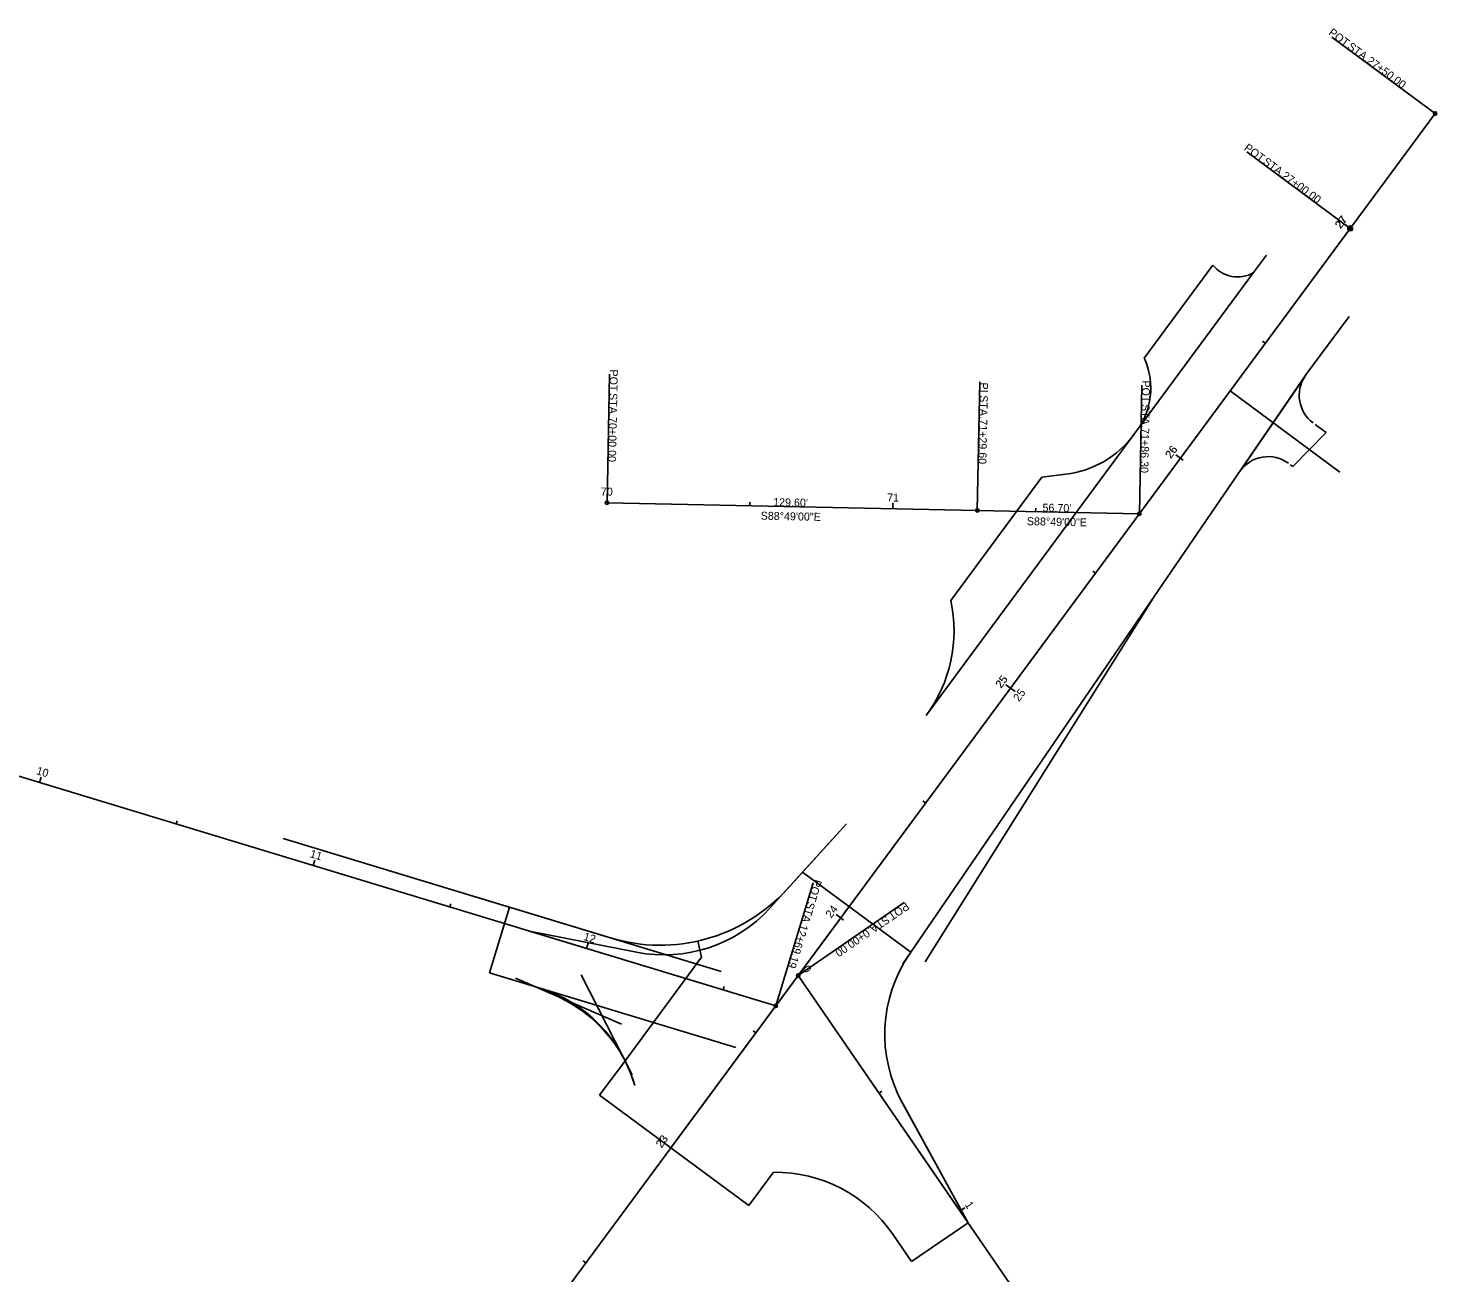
# Model space of a CAD drawing. Extents: x 1323137 to 1326838, y 458936 to 461644.
# Drawn here: x 1325088.4 to 1325581.3, y 460252 to 460687.5 of the extents above; entities that cross this region are included whole.
import ezdxf

# ---------------------------------------------------------------- set-up
doc = ezdxf.new("R2010")
doc.units = 0
for name, color, linetype in [('_CIVIL_CONSTRUCTION', 7, 'Continuous'), ('CM_Corridor_Point_Control', 7, 'Continuous'), ('CM_Corridor_Range_Final', 7, 'Continuous'), ('Default', 7, 'Continuous'), ('DT_P_Graded_Shoulder', 7, 'Continuous'), ('DT_P_Tie', 7, 'Continuous'), ('MD_P_ACB_B', 7, 'Continuous'), ('MD_P_ACB_T', 7, 'Continuous'), ('MD_P_ACSC_B', 7, 'Continuous'), ('MD_P_Surface_Asphalt_Concrete_Intermediate_Course', 7, 'Continuous'), ('PV_P_Shoulder', 7, 'Continuous'), ('RD_P_GR_Lt', 7, 'Continuous'), ('SG_P_Conduit', 7, 'Continuous'), ('SG_P_Mast_Arm', 7, 'Continuous'), ('SN_P_Signs', 7, 'Continuous'), ('SN_X_Public', 7, 'Continuous')]:
    doc.layers.add(name, color=color, linetype=linetype)

msp = doc.modelspace()

# ---------------------------------------------------------------- linework, layer by layer
at = {"layer": '_CIVIL_CONSTRUCTION'}
for p, q in [((1325551, 460617.41), (1325514.81, 460644.15)), ((1325350.01, 460345.38), (1325363.06, 460388.44))]:
    msp.add_line(p, q, dxfattribs=at)
for centre in [(1325551, 460617.41), (1325350.01, 460345.38)]:
    msp.add_circle(centre, 0.6, dxfattribs=at)
at = {"layer": 'CM_Corridor_Point_Control'}
msp.add_line((1325508.98, 460560.54), (1325547.43, 460532.13), dxfattribs=at)
at = {"layer": 'CM_Corridor_Range_Final'}
for p, q in [((1325551, 460617.41), (1325549.39, 460618.6)), ((1325521.29, 460577.19), (1325520.32, 460577.91)), ((1325491.57, 460536.98), (1325489.97, 460538.17)), ((1325461.86, 460496.77), (1325460.9, 460497.48)), ((1325432.15, 460456.55), (1325430.54, 460457.74)), ((1325092.4, 460423.47), (1325092.98, 460425.39)), ((1325402.44, 460416.34), (1325401.47, 460417.05)), ((1325140.25, 460408.97), (1325140.59, 460410.11)), ((1325188.1, 460394.46), (1325188.68, 460396.37)), ((1325235.94, 460379.95), (1325236.29, 460381.1)), ((1325372.72, 460376.12), (1325371.12, 460377.31)), ((1325283.79, 460365.45), (1325284.37, 460367.36)), ((1325331.64, 460350.94), (1325331.99, 460352.09)), ((1325343.01, 460335.91), (1325342.05, 460336.62)), ((1325313.3, 460295.7), (1325311.69, 460296.88)), ((1325283.59, 460255.48), (1325282.62, 460256.19))]:
    msp.add_line(p, q, dxfattribs=at)
at = {"layer": 'Default'}
msp.add_line((1325432.15, 460456.55), (1325432.15, 460456.55), dxfattribs=at)
msp.add_circle((1325551, 460617.41), 0.849, dxfattribs=at)
at = {"layer": 'DT_P_Tie'}
for p, q in [((1325517.2, 460601.95), (1325521.67, 460608)), ((1325476.34, 460546.65), (1325517.2, 460601.95)), ((1325478.93, 460572.03), (1325502.98, 460604.58)), ((1325535.76, 460566.5), (1325550.62, 460586.6)), ((1325479.24, 460571.28), (1325478.93, 460572.03)), ((1325397.28, 460364.2), (1325535.76, 460566.5)), ((1325512.37, 460532.33), (1325535.26, 460565.75)), ((1325538.79, 460548.76), (1325542.6, 460545.95)), ((1325402.67, 460446.95), (1325475.35, 460545.31)), ((1325475.35, 460545.31), (1325476.34, 460546.65)), ((1325530.94, 460534.06), (1325542.6, 460545.95)), ((1325530.04, 460534.73), (1325530.94, 460534.06)), ((1325411.24, 460487.15), (1325443.15, 460530.34)), ((1325443.15, 460530.34), (1325451.51, 460531.38)), ((1325402.23, 460360.81), (1325482.01, 460487.97)), ((1325347.71, 460379.29), (1325374.7, 460409.08)), ((1325374.7, 460409.08), (1325354.07, 460386.31)), ((1325374.7, 460409.08), (1325354.07, 460386.31)), ((1325359.37, 460392.2), (1325374.7, 460409.08)), ((1325330.94, 460357.42), (1325177.6, 460403.91)), ((1325292.19, 460369.17), (1325177.6, 460403.91)), ((1325292.19, 460369.17), (1325177.6, 460403.91)), ((1325347.92, 460379.57), (1325359.37, 460392.2)), ((1325347.94, 460379.6), (1325359.37, 460392.2)), ((1325397.28, 460364.2), (1325359.37, 460392.2)), ((1325313.3, 460295.7), (1325375.69, 460380.14)), ((1325256.83, 460379.89), (1325249.86, 460356.93)), ((1325292.19, 460369.17), (1325256.83, 460379.89)), ((1325263.79, 460371.51), (1325301.27, 460364.12)), ((1325263.79, 460371.51), (1325350.01, 460345.38)), ((1325263.79, 460371.51), (1325301.23, 460364.13)), ((1325394.44, 460360.08), (1325397.28, 460364.2)), ((1325397.01, 460363.8), (1325397.28, 460364.2)), ((1325336.08, 460330.79), (1325249.86, 460356.93)), ((1325267.05, 460351.71), (1325249.86, 460356.93)), ((1325267.05, 460351.71), (1325249.86, 460356.93)), ((1325299.8, 460321.27), (1325281.96, 460356.22)), ((1325357.87, 460356.02), (1325417.33, 460269.47)), ((1325258.89, 460355.04), (1325296.06, 460339.01)), ((1325272.71, 460349.08), (1325258.89, 460355.04)), ((1325272.71, 460349.08), (1325258.89, 460355.04)), ((1325288.37, 460314.12), (1325297.29, 460326.19)), ((1325299.8, 460321.27), (1325297.44, 460325.89)), ((1325340.64, 460275.49), (1325288.37, 460314.12)), ((1325393.13, 460313.52), (1325417.33, 460269.47)), ((1325394.34, 460311.33), (1325417.33, 460269.47)), ((1325417.33, 460269.47), (1325394.34, 460311.33)), ((1325340.64, 460275.49), (1325349.27, 460287.17)), ((1325397.55, 460255.88), (1325417.33, 460269.47)), ((1325390.95, 460265.49), (1325397.55, 460255.88)), ((1325397.55, 460255.88), (1325390.95, 460265.49))]:
    msp.add_line(p, q, dxfattribs=at)
for centre, radius, start, end in [((1325511.6, 460611.41), 11, 218.4165, 300.5997), ((1325456.23, 460561.51), 25, 323.5406, 23.0202), ((1325456.23, 460561.51), 25, 323.5406, 23.0202), ((1325545.16, 460558.98), 12, 145.6067, 233.5406), ((1325545.16, 460558.98), 12, 145.6067, 233.5406), ((1325447.2, 460566.11), 35, 277.0674, 323.5406), ((1325447.2, 460566.11), 35, 277.0674, 323.5406), ((1325522.28, 460525.55), 12, 53.5406, 145.6067), ((1325522.28, 460525.55), 12, 53.5406, 145.6067), ((1325362.38, 460476.55), 50, 323.6944, 12.241), ((1325309.6, 460426.59), 60, 253.1349, 317.83), ((1325309.6, 460426.59), 60, 253.1349, 317.83), ((1325309.6, 460426.59), 60, 253.1349, 317.83), ((1325310.9, 460413.18), 50, 258.844, 317.7955), ((1325438.16, 460335.4), 50, 145.3882, 208.7808), ((1325438.16, 460335.4), 50, 145.3882, 208.7808), ((1325252.55, 460303.86), 50, 15.8391, 73.1349), ((1325252.55, 460303.86), 50, 26.5217, 73.1349), ((1325252.55, 460303.86), 50, 26.5217, 73.1349), ((1325252.91, 460303.16), 50, 27.0403, 66.6704), ((1325252.91, 460303.16), 50, 27.0403, 66.6704), ((1325252.91, 460303.16), 50, 27.4251, 66.6704), ((1325252.55, 460303.86), 50, 15.8391, 26.5217), ((1325349.74, 460237.17), 50, 34.4914, 90.5294)]:
    msp.add_arc(centre, radius, start, end, dxfattribs=at)
at = {"layer": 'MD_P_ACB_B'}
for p, q in [((1325580.71, 460657.62), (1325544.52, 460684.36)), ((1325290.96, 460521.4), (1325291.89, 460566.39)), ((1325420.53, 460518.72), (1325421.46, 460563.71)), ((1325477.22, 460517.55), (1325478.15, 460562.54)), ((1325357.87, 460356.02), (1325394.96, 460381.5))]:
    msp.add_line(p, q, dxfattribs=at)
for centre in [(1325580.71, 460657.62), (1325290.96, 460521.4), (1325420.53, 460518.72), (1325477.22, 460517.55), (1325357.87, 460356.02)]:
    msp.add_circle(centre, 0.6, dxfattribs=at)
at = {"layer": 'MD_P_ACSC_B'}
msp.add_line((1325580.71, 460657.62), (1325544.52, 460684.36), dxfattribs=at)
msp.add_circle((1325580.71, 460657.62), 0.6, dxfattribs=at)
at = {"layer": 'MD_P_Surface_Asphalt_Concrete_Intermediate_Course'}
for p, q in [((1325551, 460617.41), (1325514.81, 460644.15)), ((1325350.01, 460345.38), (1325363.06, 460388.44))]:
    msp.add_line(p, q, dxfattribs=at)
for centre in [(1325551, 460617.41), (1325350.01, 460345.38)]:
    msp.add_circle(centre, 0.6, dxfattribs=at)
at = {"layer": 'PV_P_Shoulder'}
for p, q in [((1325551, 460617.41), (1325551.96, 460616.69)), ((1325491.57, 460536.98), (1325492.54, 460536.27)), ((1325432.15, 460456.55), (1325433.76, 460455.36)), ((1325372.72, 460376.12), (1325373.69, 460375.41)), ((1325313.3, 460295.7), (1325314.26, 460294.98))]:
    msp.add_line(p, q, dxfattribs=at)
at = {"layer": 'RD_P_GR_Lt'}
for p, q in [((1325324.02, 460362.37), (1325322.75, 460368.05)), ((1325294.69, 460322.67), (1325324.02, 460362.37))]:
    msp.add_line(p, q, dxfattribs=at)
at = {"layer": 'SG_P_Conduit'}
for p, q in [((1324897.32, 459732.7), (1325580.71, 460657.62)), ((1325290.96, 460521.4), (1325420.53, 460518.72)), ((1325290.96, 460521.4), (1325420.53, 460518.72)), ((1325420.53, 460518.72), (1325477.22, 460517.55)), ((1325420.53, 460518.72), (1325477.22, 460517.55)), ((1325357.87, 460356.02), (1325558, 460064.72))]:
    msp.add_line(p, q, dxfattribs=at)
at = {"layer": 'SG_P_Mast_Arm'}
for p, q in [((1325580.71, 460657.62), (1325579.75, 460658.33)), ((1325551, 460617.41), (1325549.39, 460618.6)), ((1325521.29, 460577.19), (1325520.32, 460577.91)), ((1325491.57, 460536.98), (1325489.97, 460538.17)), ((1325290.96, 460521.4), (1325291, 460523.4)), ((1325340.95, 460520.37), (1325340.97, 460521.57)), ((1325390.93, 460519.34), (1325390.98, 460521.33)), ((1325440.92, 460518.3), (1325440.95, 460519.5)), ((1325461.86, 460496.77), (1325460.9, 460497.48)), ((1325432.15, 460456.55), (1325430.54, 460457.74)), ((1325402.44, 460416.34), (1325401.47, 460417.05)), ((1325372.72, 460376.12), (1325371.12, 460377.31)), ((1325357.87, 460356.02), (1325359.52, 460357.15)), ((1325343.01, 460335.91), (1325342.05, 460336.62)), ((1325386.18, 460314.81), (1325387.17, 460315.49)), ((1325313.3, 460295.7), (1325311.69, 460296.88)), ((1325414.5, 460273.6), (1325416.14, 460274.73)), ((1325283.59, 460255.48), (1325282.62, 460256.19))]:
    msp.add_line(p, q, dxfattribs=at)
at = {"layer": 'SN_P_Signs'}
for p, q in [((1324897.32, 459732.7), (1325551, 460617.41)), ((1324802.88, 460511.24), (1325350.01, 460345.38)), ((1325357.87, 460356.02), (1325558, 460064.72))]:
    msp.add_line(p, q, dxfattribs=at)
at = {"layer": 'SN_X_Public'}
for p, q in [((1325551, 460617.41), (1325550.03, 460618.12)), ((1325491.57, 460536.98), (1325490.61, 460537.69)), ((1325432.15, 460456.55), (1325430.54, 460457.74)), ((1325092.4, 460423.47), (1325092.98, 460425.39)), ((1325188.1, 460394.46), (1325188.44, 460395.61)), ((1325372.72, 460376.12), (1325371.76, 460376.84)), ((1325283.79, 460365.45), (1325284.14, 460366.6)), ((1325313.3, 460295.7), (1325312.33, 460296.41))]:
    msp.add_line(p, q, dxfattribs=at)

# ---------------------------------------------------------------- texts
at = {"layer": '_CIVIL_CONSTRUCTION'}
for s, rotation, p in [('POT', 323.5406, (1325513.63, 460645.06)), (' STA. ', 323.5406, (1325519.37, 460640.82)), ('27+00.00', 323.5406, (1325526.87, 460635.28)), ('POT', 253.1349, (1325363.51, 460389.81)), (' STA. ', 253.1349, (1325361.45, 460382.99)), ('12+69.19', 253.1349, (1325358.74, 460374.06))]:
    msp.add_text(s, height=2.8, rotation=rotation, dxfattribs=at).set_placement(p)
at = {"layer": 'CM_Corridor_Range_Final'}
for s, rotation, p in [('27', 53.5406, (1325547.73, 460617.18)), ('26', 53.5406, (1325488.29, 460536.75)), ('25', 53.5406, (1325428.9, 460456.36)), ('10', 343.1349, (1325091.06, 460426.49)), ('11', 343.1349, (1325186.8, 460397.46)), ('24', 53.5406, (1325369.43, 460375.87)), ('12', 343.1349, (1325282.52, 460368.45)), ('23', 53.5406, (1325310.05, 460295.51))]:
    msp.add_text(s, height=2.8, rotation=rotation, dxfattribs=at).set_placement(p)
at = {"layer": 'DT_P_Graded_Shoulder'}
for p in [(1325344.71, 460515.49), (1325437.84, 460513.57)]:
    msp.add_text('S88°49\'00"E', height=2.8, rotation=358.8166, dxfattribs=at).set_placement(p)
at = {"layer": 'MD_P_ACB_B'}
for s, rotation, p in [('POT', 323.5406, (1325543.19, 460685.4)), (' STA. ', 323.5406, (1325548.98, 460681.12)), ('27+50.00', 323.5406, (1325556.59, 460675.5)), ('POT', 268.8166, (1325291.96, 460568.07)), ('PI', 268.8166, (1325421.5, 460563.49)), ('POT', 268.8166, (1325478.23, 460564.22)), (' STA. ', 268.8166, (1325291.81, 460560.87)), (' STA. ', 268.8166, (1325421.43, 460560.1)), (' STA. ', 268.8166, (1325478.08, 460557.02)), ('70+00.00', 268.8166, (1325291.62, 460551.42)), ('71+29.60', 268.8166, (1325421.23, 460550.65)), ('71+86.30', 268.8166, (1325477.88, 460547.57)), ('POT', 214.4914, (1325395.45, 460381.78)), (' STA. ', 214.4914, (1325389.51, 460377.71)), ('0+00.00', 214.4914, (1325381.72, 460372.35))]:
    msp.add_text(s, height=2.8, rotation=rotation, dxfattribs=at).set_placement(p)
at = {"layer": 'MD_P_ACB_T'}
for s, p in [("129.60'", (1325349.07, 460520.24)), ("56.70'", (1325443.32, 460518.3))]:
    msp.add_text(s, height=2.8, rotation=358.8166, dxfattribs=at).set_placement(p)
at = {"layer": 'MD_P_ACSC_B'}
for s, p in [('POT', (1325543.19, 460685.4)), (' STA. ', (1325548.98, 460681.12)), ('27+50.00', (1325556.59, 460675.5))]:
    msp.add_text(s, height=2.8, rotation=323.5406, dxfattribs=at).set_placement(p)
at = {"layer": 'MD_P_Surface_Asphalt_Concrete_Intermediate_Course'}
for s, rotation, p in [('POT', 323.5406, (1325513.63, 460645.06)), (' STA. ', 323.5406, (1325519.37, 460640.82)), ('27+00.00', 323.5406, (1325526.87, 460635.28)), ('POT', 253.1349, (1325363.51, 460389.81)), (' STA. ', 253.1349, (1325361.45, 460382.99)), ('12+69.19', 253.1349, (1325358.74, 460374.06))]:
    msp.add_text(s, height=2.8, rotation=rotation, dxfattribs=at).set_placement(p)
at = {"layer": 'PV_P_Shoulder'}
msp.add_text('25', height=2.8, rotation=53.5406, dxfattribs=at).set_placement((1325435.11, 460451.64))
at = {"layer": 'SG_P_Mast_Arm'}
for s, rotation, p in [('27', 53.5406, (1325547.62, 460617.04)), ('26', 53.5406, (1325488.23, 460536.66)), ('70', 358.8166, (1325288.78, 460523.95)), ('71', 358.8166, (1325388.95, 460521.88)), ('25', 53.5406, (1325428.84, 460456.28)), ('24', 53.5406, (1325369.43, 460375.88)), ('0', 304.4914, (1325359.3, 460358.35)), ('23', 53.5406, (1325310.01, 460295.45)), ('1', 304.4914, (1325416.04, 460275.77))]:
    msp.add_text(s, height=2.8, rotation=rotation, dxfattribs=at).set_placement(p)
at = {"layer": 'SN_X_Public'}
for s, rotation, p in [('25', 53.5406, (1325428.9, 460456.36)), ('10', 343.1349, (1325091.06, 460426.49))]:
    msp.add_text(s, height=2.8, rotation=rotation, dxfattribs=at).set_placement(p)

doc.saveas('drawing.dxf')
